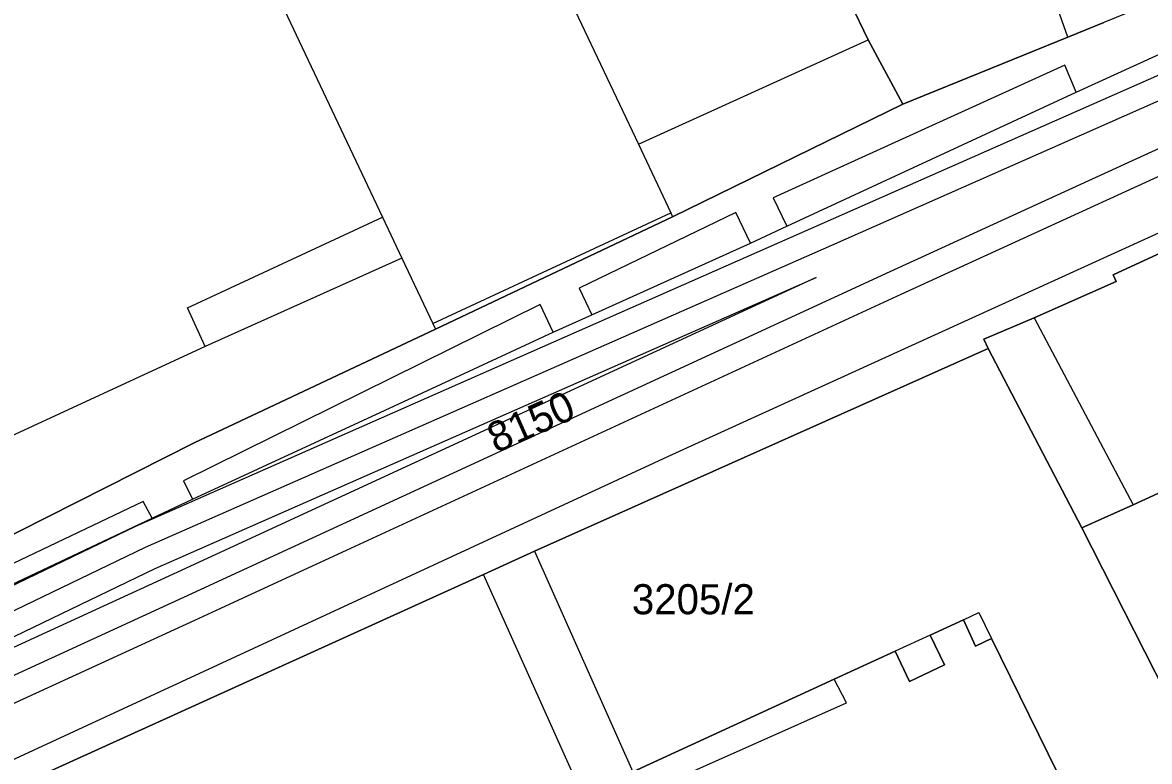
# Model space of a CAD drawing. Extents: x -264070 to -262271, y -1238894 to -1238141.
# Drawn here: x -263050.9 to -262975.9, y -1238614.4 to -1238565.3 of the extents above; entities that cross this region are included whole.
import ezdxf

# ---------------------------------------------------------------- set-up
doc = ezdxf.new("R2010")
doc.units = 0
for name, color, linetype in [('body_kn', 7, 'Continuous'), ('kladpar_druhypozemkov', 7, 'Continuous'), ('kladpar_hranice', 7, 'Continuous'), ('kladpar_parcelnecisla', 7, 'Continuous'), ('kladpar_plochy', 7, 'Continuous'), ('tarchy_linie', 7, 'Continuous'), ('zappar_hrandruhpozemk', 7, 'Continuous')]:
    doc.layers.add(name, color=color, linetype=linetype)

msp = doc.modelspace()

# ---------------------------------------------------------------- linework, layer by layer
at = {"layer": 'body_kn'}
for p, q in [((-262994.61, -1238566.47), (-262994.61, -1238566.47)), ((-262981.34, -1238566.3), (-262981.34, -1238566.3)), ((-262981.34, -1238566.3), (-262981.34, -1238566.3)), ((-262981.53, -1238568.15), (-262981.53, -1238568.15)), ((-262980.78, -1238569.95), (-262980.78, -1238569.95)), ((-262980.78, -1238569.95), (-262980.78, -1238569.95)), ((-262992.31, -1238570.76), (-262992.31, -1238570.76)), ((-263009.89, -1238573.41), (-263009.89, -1238573.41)), ((-263000.94, -1238576.97), (-263000.94, -1238576.97)), ((-263000.94, -1238576.97), (-263000.94, -1238576.97)), ((-263007.75, -1238577.98), (-263007.75, -1238577.98)), ((-263003.41, -1238577.95), (-263003.41, -1238577.95)), ((-263026.91, -1238578.25), (-263026.91, -1238578.25)), ((-263026.91, -1238578.25), (-263026.91, -1238578.25)), ((-263007.62, -1238578.23), (-263007.62, -1238578.23)), ((-263007.62, -1238578.23), (-263007.62, -1238578.23)), ((-263000.02, -1238578.86), (-263000.02, -1238578.86)), ((-263000.02, -1238578.86), (-263000.02, -1238578.86)), ((-262997.67, -1238578.69), (-262997.67, -1238578.69)), ((-263002.45, -1238579.98), (-263002.45, -1238579.98)), ((-262997.04, -1238580.11), (-262997.04, -1238580.11)), ((-263025.64, -1238580.99), (-263025.64, -1238580.99)), ((-263025.64, -1238580.99), (-263025.64, -1238580.99)), ((-262993.15, -1238581.86), (-262993.15, -1238581.86)), ((-262998.07, -1238582.26), (-262998.07, -1238582.26)), ((-262978.33, -1238582.09), (-262978.33, -1238582.09)), ((-262978.13, -1238582.53), (-262978.13, -1238582.53)), ((-263013.83, -1238582.98), (-263013.83, -1238582.98)), ((-262992.44, -1238583.4), (-262992.44, -1238583.4)), ((-263016.44, -1238584.06), (-263016.44, -1238584.06)), ((-263016.44, -1238584.06), (-263016.44, -1238584.06)), ((-263039.89, -1238584.29), (-263039.89, -1238584.29)), ((-263012.99, -1238584.74), (-263012.99, -1238584.74)), ((-263012.99, -1238584.74), (-263012.99, -1238584.74)), ((-263023.58, -1238585.32), (-263023.58, -1238585.32)), ((-263023.58, -1238585.32), (-263023.58, -1238585.32)), ((-262983.58, -1238584.94), (-262983.58, -1238584.94)), ((-262983.58, -1238584.94), (-262983.58, -1238584.94)), ((-263023.4, -1238585.7), (-263023.4, -1238585.7)), ((-263015.56, -1238585.9), (-263015.56, -1238585.9)), ((-263015.56, -1238585.9), (-263015.56, -1238585.9)), ((-262986.93, -1238586.37), (-262986.93, -1238586.37)), ((-263038.72, -1238586.85), (-263038.72, -1238586.85)), ((-262986.63, -1238586.99), (-262986.63, -1238586.99)), ((-263026.74, -1238591.08), (-263026.74, -1238591.08)), ((-263039.44, -1238593.26), (-263039.44, -1238593.26)), ((-263007.66, -1238594.03), (-263007.66, -1238594.03)), ((-263040.16, -1238595.79), (-263040.16, -1238595.79)), ((-263042.84, -1238597.15), (-263042.84, -1238597.15)), ((-263039.56, -1238597.01), (-263039.56, -1238597.01)), ((-263039.56, -1238597.01), (-263039.56, -1238597.01)), ((-262976.99, -1238597.37), (-262976.99, -1238597.37)), ((-263042.23, -1238598.27), (-263042.23, -1238598.27)), ((-263043.33, -1238598.79), (-263043.33, -1238598.79)), ((-262980.41, -1238598.9), (-262980.41, -1238598.9)), ((-263042.68, -1238600.2), (-263042.68, -1238600.2)), ((-263016.81, -1238600.45), (-263016.81, -1238600.45)), ((-263016.81, -1238600.45), (-263016.81, -1238600.45)), ((-263042.03, -1238601.61), (-263042.03, -1238601.61)), ((-263042.03, -1238601.61), (-263042.03, -1238601.61)), ((-263040.85, -1238601.98), (-263040.85, -1238601.98)), ((-263020.21, -1238602), (-263020.21, -1238602)), ((-263040.14, -1238603.52), (-263040.14, -1238603.52)), ((-263039.43, -1238605.06), (-263039.43, -1238605.06)), ((-262988.27, -1238605.01), (-262988.27, -1238605.01)), ((-262988.27, -1238605.01), (-262988.27, -1238605.01)), ((-262987.25, -1238604.54), (-262987.25, -1238604.54)), ((-262990.49, -1238606.03), (-262990.49, -1238606.03)), ((-262990.49, -1238606.03), (-262990.49, -1238606.03)), ((-262986.41, -1238606.26), (-262986.41, -1238606.26)), ((-262992.82, -1238607.1), (-262992.82, -1238607.1)), ((-262987.48, -1238606.76), (-262987.48, -1238606.76)), ((-262989.54, -1238608.02), (-262989.54, -1238608.02)), ((-262996.87, -1238608.96), (-262996.87, -1238608.96)), ((-262991.87, -1238609.12), (-262991.87, -1238609.12)), ((-262996.05, -1238610.53), (-262996.05, -1238610.53))]:
    msp.add_line(p, q, dxfattribs=at)
at = {"layer": 'kladpar_druhypozemkov'}
for p, q in [((-263018.02, -1238591.14), (-263018.02, -1238591.14)), ((-263004.85, -1238602.37), (-263004.85, -1238602.37))]:
    msp.add_line(p, q, dxfattribs=at)
at = {"layer": 'kladpar_hranice'}
for points in [[(-263065.7, -1238550.9), (-263056.86, -1238547.07), (-263054.34, -1238545.86), (-263028.95, -1238533.25), (-263017.61, -1238527.12), (-263004.42, -1238548.18), (-262996.97, -1238561.58), (-262994.61, -1238566.47), (-262992.31, -1238570.76), (-263007.62, -1238578.23), (-263023.4, -1238585.7), (-263039.44, -1238593.26), (-263060.96, -1238604.1), (-263078.37, -1238612.51), (-263081.2, -1238606.5), (-263095.23, -1238576.97), (-263101.57, -1238563.43), (-263095.51, -1238560.38), (-263093.44, -1238564.6), (-263087.21, -1238561.28), (-263083.52, -1238559.32), (-263065.7, -1238550.9)], [(-262988.56, -1238554.22), (-262986.39, -1238553.32), (-262986.69, -1238552.57), (-262980.66, -1238550.13), (-262979.19, -1238549.53), (-262978.6, -1238550.99), (-262975.03, -1238549.52), (-262973.99, -1238552.12), (-262969.49, -1238550.26), (-262964.72, -1238559.53), (-262978.93, -1238565.32), (-262981.34, -1238566.3), (-262992.31, -1238570.76), (-262994.61, -1238566.47), (-262996.97, -1238561.58), (-262993.62, -1238560.2), (-262994.83, -1238557.46), (-262988.28, -1238554.83), (-262988.56, -1238554.22)], [(-262934.31, -1238562.47), (-262949.95, -1238569.62), (-262965.81, -1238576.98), (-262974.61, -1238580.95), (-262974.82, -1238580.47), (-262978.33, -1238582.09), (-262978.13, -1238582.53), (-262983.58, -1238584.94), (-262986.93, -1238586.37), (-262986.63, -1238586.99), (-263016.81, -1238600.45), (-263020.21, -1238602), (-263050.35, -1238615.68)], [(-263007.62, -1238578.23), (-262992.31, -1238570.76), (-262981.34, -1238566.3), (-262978.93, -1238565.32)], [(-262965.81, -1238576.98), (-262960.21, -1238589.66), (-262976.99, -1238597.37), (-262980.41, -1238598.9), (-262986.63, -1238586.99), (-262986.93, -1238586.37), (-262983.58, -1238584.94), (-262978.13, -1238582.53), (-262978.33, -1238582.09), (-262974.82, -1238580.47), (-262974.61, -1238580.95), (-262965.81, -1238576.98)], [(-263084.41, -1238615.48), (-263078.37, -1238612.51), (-263060.96, -1238604.1), (-263039.44, -1238593.26), (-263023.4, -1238585.7), (-263007.62, -1238578.23)], [(-263050.35, -1238615.68), (-263020.21, -1238602), (-263016.81, -1238600.45), (-262986.63, -1238586.99), (-262980.41, -1238598.9), (-262969.23, -1238620.88)], [(-262960.21, -1238589.66), (-262959.39, -1238591.38), (-262957.89, -1238594.66), (-262956.39, -1238598.05), (-262956.3, -1238598.3), (-262955.85, -1238599.27), (-262949.83, -1238613.04), (-262969.23, -1238620.88), (-262980.41, -1238598.9), (-262976.99, -1238597.37), (-262960.21, -1238589.66)], [(-262978.88, -1238621.59), (-262978.2, -1238622.99), (-262993.97, -1238629.43), (-262996.2, -1238630.39), (-263000.97, -1238632.43), (-263003.89, -1238633.64), (-263026.91, -1238643.19), (-263027.76, -1238641.45), (-263035, -1238626.43), (-263034.44, -1238626.17), (-263033.61, -1238625.79), (-263029.46, -1238623.89), (-263013.62, -1238616.66), (-263010.26, -1238615.11), (-262996.87, -1238608.96), (-262992.82, -1238607.1), (-262991.87, -1238609.12), (-262989.54, -1238608.02), (-262990.49, -1238606.03), (-262988.27, -1238605.01), (-262987.48, -1238606.76), (-262986.41, -1238606.26), (-262978.88, -1238621.59)], [(-262978.88, -1238621.59), (-262986.41, -1238606.26), (-262987.48, -1238606.76), (-262988.27, -1238605.01), (-262990.49, -1238606.03), (-262989.54, -1238608.02), (-262991.87, -1238609.12), (-262992.82, -1238607.1), (-262996.87, -1238608.96), (-263010.26, -1238615.11)]]:
    msp.add_lwpolyline(points, dxfattribs=at)
at = {"layer": 'kladpar_plochy'}
for p, q in [((-262990.49, -1238606.03), (-262988.27, -1238605.01)), ((-262988.27, -1238605.01), (-262987.48, -1238606.76)), ((-262989.54, -1238608.02), (-262990.49, -1238606.03)), ((-262987.48, -1238606.76), (-262986.41, -1238606.26)), ((-262986.41, -1238606.26), (-262978.88, -1238621.59)), ((-262996.87, -1238608.96), (-262992.82, -1238607.1)), ((-262992.82, -1238607.1), (-262991.87, -1238609.12)), ((-262991.87, -1238609.12), (-262989.54, -1238608.02)), ((-263010.26, -1238615.11), (-262996.87, -1238608.96))]:
    msp.add_line(p, q, dxfattribs=at)
for points in [[(-263065.7, -1238550.9), (-263056.86, -1238547.07), (-263054.34, -1238545.86), (-263028.95, -1238533.25), (-263017.61, -1238527.12), (-263004.42, -1238548.18), (-262996.97, -1238561.58), (-262994.61, -1238566.47), (-262992.31, -1238570.76), (-263007.62, -1238578.23), (-263023.4, -1238585.7), (-263039.44, -1238593.26), (-263060.96, -1238604.1), (-263078.37, -1238612.51), (-263081.2, -1238606.5), (-263095.23, -1238576.97), (-263101.57, -1238563.43), (-263095.51, -1238560.38), (-263093.44, -1238564.6), (-263087.21, -1238561.28), (-263083.52, -1238559.32)], [(-262988.56, -1238554.22), (-262986.39, -1238553.32), (-262986.69, -1238552.57), (-262980.66, -1238550.13), (-262979.19, -1238549.53), (-262978.6, -1238550.99), (-262975.03, -1238549.52), (-262973.99, -1238552.12), (-262969.49, -1238550.26), (-262964.72, -1238559.53), (-262978.93, -1238565.32), (-262981.34, -1238566.3), (-262992.31, -1238570.76), (-262994.61, -1238566.47), (-262996.97, -1238561.58), (-262993.62, -1238560.2), (-262994.83, -1238557.46), (-262988.28, -1238554.83)], [(-262965.81, -1238576.98), (-262960.21, -1238589.66), (-262976.99, -1238597.37), (-262980.41, -1238598.9), (-262986.63, -1238586.99), (-262986.93, -1238586.37), (-262983.58, -1238584.94), (-262978.13, -1238582.53), (-262978.33, -1238582.09), (-262974.82, -1238580.47), (-262974.61, -1238580.95)], [(-262960.21, -1238589.66), (-262959.39, -1238591.38), (-262957.89, -1238594.66), (-262956.39, -1238598.05), (-262956.3, -1238598.3), (-262955.85, -1238599.27), (-262949.83, -1238613.04), (-262969.23, -1238620.88), (-262980.41, -1238598.9), (-262976.99, -1238597.37)]]:
    msp.add_lwpolyline(points, close=True, dxfattribs=at)
for points in [[(-262934.31, -1238562.47), (-262949.95, -1238569.62), (-262965.81, -1238576.98), (-262974.61, -1238580.95), (-262974.82, -1238580.47), (-262978.33, -1238582.09), (-262978.13, -1238582.53), (-262983.58, -1238584.94), (-262986.93, -1238586.37), (-262986.63, -1238586.99), (-263016.81, -1238600.45), (-263020.21, -1238602), (-263050.35, -1238615.68)], [(-263060.96, -1238604.1), (-263039.44, -1238593.26), (-263023.4, -1238585.7), (-263007.62, -1238578.23), (-262992.31, -1238570.76), (-262981.34, -1238566.3), (-262978.93, -1238565.32)], [(-263050.35, -1238615.68), (-263020.21, -1238602), (-263016.81, -1238600.45), (-262986.63, -1238586.99), (-262980.41, -1238598.9), (-262969.23, -1238620.88)], [(-262978.88, -1238621.59), (-262986.41, -1238606.26), (-262987.48, -1238606.76), (-262988.27, -1238605.01), (-262990.49, -1238606.03), (-262989.54, -1238608.02), (-262991.87, -1238609.12), (-262992.82, -1238607.1), (-262996.87, -1238608.96), (-263010.26, -1238615.11)]]:
    msp.add_lwpolyline(points, dxfattribs=at)
at = {"layer": 'tarchy_linie'}
for points in [[(-263127.28, -1238639.92), (-263086.66, -1238619.65), (-263043.33, -1238598.79), (-262997.67, -1238578.69), (-262948.78, -1238557.1), (-262916.97, -1238543.57), (-262916.75, -1238544.13), (-262916.4, -1238545.02), (-262915.51, -1238547.31), (-262914.89, -1238548.89), (-262945.47, -1238561.89), (-262992.44, -1238583.4), (-263039.43, -1238605.06), (-263086.63, -1238626.71), (-263123.25, -1238643.79), (-263125.06, -1238644.64), (-263125.78, -1238643.09), (-263126.6, -1238641.32), (-263127.07, -1238640.31), (-263127.28, -1238639.92)], [(-263126.6, -1238641.32), (-263085.98, -1238621.04), (-263042.68, -1238600.2), (-262997.04, -1238580.11), (-262948.16, -1238558.52), (-262916.4, -1238545.02)], [(-263123.97, -1238642.25), (-263087.34, -1238625.17), (-263040.14, -1238603.52), (-262993.15, -1238581.86), (-262946.16, -1238560.33), (-262915.51, -1238547.31)], [(-263042.03, -1238601.61), (-262998.07, -1238582.26), (-263040.85, -1238601.98), (-263082.57, -1238621.12), (-263042.03, -1238601.61)]]:
    msp.add_lwpolyline(points, dxfattribs=at)
at = {"layer": 'zappar_hrandruhpozemk'}
for p, q in [((-263025.75, -1238539.93), (-263009.89, -1238573.41)), ((-263040.4, -1238549.81), (-263026.91, -1238578.25)), ((-262981.34, -1238566.3), (-262984.78, -1238556.56)), ((-263009.89, -1238573.41), (-262994.61, -1238566.47)), ((-263007.66, -1238594.03), (-262962.12, -1238573.29)), ((-263000.94, -1238576.97), (-263000.02, -1238578.86)), ((-263023.58, -1238585.32), (-263007.75, -1238577.98)), ((-263039.89, -1238584.29), (-263026.91, -1238578.25)), ((-263002.45, -1238579.98), (-263000.02, -1238578.86)), ((-263012.99, -1238584.74), (-263002.45, -1238579.98)), ((-263025.64, -1238580.99), (-263038.72, -1238586.85)), ((-263015.56, -1238585.9), (-263016.44, -1238584.06)), ((-263038.72, -1238586.85), (-263039.89, -1238584.29)), ((-262983.58, -1238584.94), (-262976.99, -1238597.37)), ((-263038.72, -1238586.85), (-263081.2, -1238606.5)), ((-263039.56, -1238597.01), (-263026.74, -1238591.08)), ((-263091.6, -1238632.85), (-263007.66, -1238594.03)), ((-263042.23, -1238598.27), (-263039.56, -1238597.01)), ((-263016.81, -1238600.45), (-263010.26, -1238615.11)), ((-263013.62, -1238616.66), (-263020.21, -1238602)), ((-262988.27, -1238605.01), (-262987.25, -1238604.54)), ((-262987.25, -1238604.54), (-262986.41, -1238606.26)), ((-262990.49, -1238606.03), (-262992.82, -1238607.1)), ((-262996.05, -1238610.53), (-262996.87, -1238608.96)), ((-263008.93, -1238616.25), (-262996.05, -1238610.53))]:
    msp.add_line(p, q, dxfattribs=at)
for points in [[(-263000.02, -1238578.86), (-262980.78, -1238569.95), (-262949.77, -1238555.79)], [(-262980.78, -1238569.95), (-262981.53, -1238568.15), (-263000.94, -1238576.97)], [(-263009.89, -1238573.41), (-263007.75, -1238577.98), (-263007.62, -1238578.23)], [(-263002.45, -1238579.98), (-263003.41, -1238577.95), (-263013.83, -1238582.98), (-263012.99, -1238584.74)], [(-263026.91, -1238578.25), (-263025.64, -1238580.99), (-263023.58, -1238585.32), (-263023.4, -1238585.7)], [(-263016.44, -1238584.06), (-263040.16, -1238595.79), (-263039.56, -1238597.01)], [(-263026.74, -1238591.08), (-263015.56, -1238585.9), (-263012.99, -1238584.74)], [(-263042.23, -1238598.27), (-263042.84, -1238597.15), (-263070.7, -1238610.43), (-263070.26, -1238611.49)], [(-263095.67, -1238623.23), (-263070.26, -1238611.49), (-263042.23, -1238598.27)]]:
    msp.add_lwpolyline(points, dxfattribs=at)

# ---------------------------------------------------------------- texts
at = {"layer": 'kladpar_parcelnecisla'}
msp.add_text('8150', height=2, rotation=24, dxfattribs=at).set_placement((-263019.368, -1238593.97))
msp.add_text('3205/2', height=2, dxfattribs=at).set_placement((-263010.332, -1238604.65))

doc.saveas('drawing.dxf')
